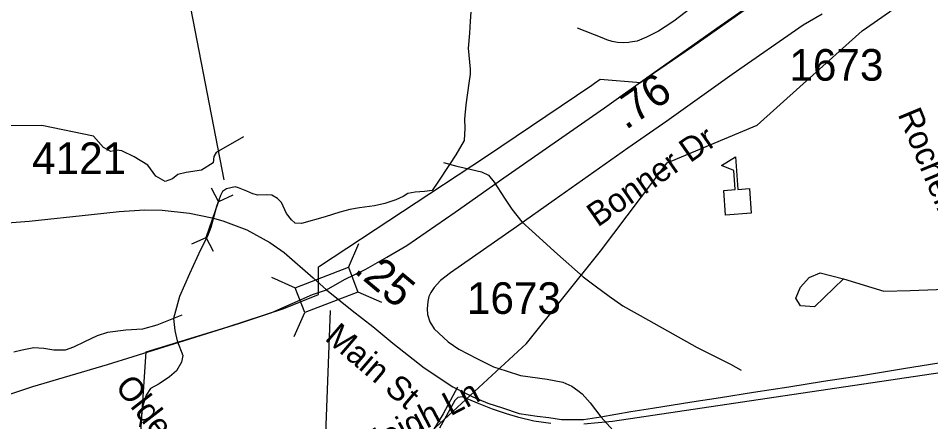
# Model space of a CAD drawing. Extents: x 1662474 to 1856135, y 779280 to 917889.
# Drawn here: x 1725036 to 1728645, y 818661 to 820256 of the extents above; entities that cross this region are included whole.
import ezdxf

# ---------------------------------------------------------------- set-up
doc = ezdxf.new("R2010")
doc.units = 0
for name, color, linetype in [('Exist Boundary Political City Limit New', 7, 'Continuous'), ('Exist Cultural Educational Facility High CELL', 7, 'Continuous'), ('Exist Hydrographic Creek Single Shore', 7, 'Continuous'), ('Exist Hydrographic Misc Water Feature', 7, 'Continuous'), ('Exist Railroad Mainline', 7, 'Continuous'), ('Exist Railroad Structure Bridge Number Label', 7, 'Continuous'), ('Exist Road Non-System Type 51', 7, 'Continuous'), ('Exist Road Non-System Type 51 Label', 7, 'Continuous'), ('Exist Road Secondary Mileage Hundredths English Label', 7, 'Continuous'), ('Exist Road Secondary Structure Culvert CELL', 7, 'Continuous'), ('Exist Road Secondary Structure Culvert Number Label', 7, 'Continuous'), ('Exist Road Secondary Structure RailRoad CELL', 7, 'Continuous'), ('Exist Road Secondary Type 51 Attributed', 7, 'Continuous'), ('Exist Road Secondary Type 51 Label', 7, 'Continuous'), ('Exist Road Secondary Type 51 Number Label', 7, 'Continuous'), ('Exist Utilities Electrical Transmission Line', 7, 'Continuous'), ('Map Preparation Boundary City Limit Buffer Line', 7, 'Continuous')]:
    doc.layers.add(name, color=color, linetype=linetype)

msp = doc.modelspace()

# ---------------------------------------------------------------- linework, layer by layer
at = {"layer": 'Exist Boundary Political City Limit New'}
for points in [[(1725521, 818621.9), (1725542, 818938.2), (1725684.2, 818981.4), (1725861.2, 819035.5), (1726086, 819108.9), (1726222.9, 819164.1), (1726223.8, 819273.9), (1726227.1, 819276), (1726883.2, 819708.8), (1727305, 819992.4), (1727314.8, 820000), (1727336.9, 820015.2), (1727496.4, 820002.2), (1727523.6, 820021.5), (1727698.1, 820142.2), (1728114.9, 820435.6)], [(1728753.6, 818865.6), (1727997.5, 818753.7), (1727386.4, 818662.2), (1727273.2, 818651.4)], [(1727141.9, 818654), (1727075.5, 818663), (1727015.8, 818677.4), (1726966.2, 818693), (1726911.8, 818711.2), (1726851.9, 818734.7), (1726793.4, 818759.4), (1726773.9, 818756.8), (1726767.4, 818750.2), (1726762.1, 818745), (1726702.4, 818635.8)]]:
    msp.add_lwpolyline(points, dxfattribs=at)
at = {"layer": 'Exist Cultural Educational Facility High CELL'}
msp.add_lwpolyline([(1727833, 819478.2), (1727825.9, 819575.8), (1727871.8, 819579.2), (1727866.3, 819654.1), (1727817.6, 819674.8), (1727872, 819708.1), (1727881.3, 819579.9), (1727927.3, 819583.2), (1727934.4, 819485.6)], close=True, dxfattribs=at)
at = {"layer": 'Exist Hydrographic Creek Single Shore'}
msp.add_lwpolyline([(1726826.2, 820280.7), (1726823.4, 820244.8), (1726820.2, 820197.2), (1726814.8, 820137.9), (1726823.6, 820054.7), (1726822.6, 820035.6), (1726817.4, 820000.1), (1726805.8, 819914), (1726800.8, 819857.3), (1726802.1, 819821.9), (1726799, 819772.8), (1726766.6, 819716.6), (1726741.8, 819678.3), (1726695.8, 819608.2), (1726673, 819576), (1726643, 819571.2), (1726606, 819568.4), (1726576.6, 819563.1), (1726558.5, 819551.3), (1726529.1, 819537.9), (1726486.1, 819523.8), (1726444.6, 819515.1), (1726385.6, 819506.9), (1726347.2, 819500.4), (1726308.1, 819489.9), (1726249.6, 819471), (1726155.6, 819445), (1726130.5, 819446.8), (1726116.5, 819458.9), (1726096.9, 819484.9), (1726076.6, 819527.4), (1726061.1, 819543.9), (1726039.1, 819556.8), (1726016.2, 819558.4), (1725982.8, 819556.8), (1725963.2, 819562.6), (1725939.6, 819572.3), (1725906.9, 819585.4), (1725893.2, 819590.1), (1725859.6, 819582), (1725843.4, 819571.2), (1725836, 819556), (1725828.9, 819536.6), (1725819.8, 819511.9), (1725797.1, 819429.5), (1725784.5, 819394.4), (1725756.1, 819340.6), (1725712.9, 819245.6), (1725673.8, 819156.8), (1725650.1, 819068.9), (1725655.6, 819021.6), (1725664.9, 818981.5), (1725686.6, 818922.7), (1725681.1, 818896.4), (1725661.8, 818862.3), (1725633.6, 818838.7), (1725592.9, 818811.7), (1725558.8, 818792.5), (1725542.2, 818766), (1725528.6, 818724.3), (1725515.5, 818641.1)], dxfattribs=at)
at = {"layer": 'Exist Hydrographic Misc Water Feature'}
for points in [[(1725926.6, 819787.1), (1725819, 819725), (1725809.9, 819709.9), (1725806.9, 819684.1), (1725759.9, 819655.4), (1725699.3, 819646.3), (1725666.8, 819638.7), (1725645.6, 819622), (1725616.8, 819611.4), (1725580.5, 819632.6), (1725548.6, 819675), (1725494.1, 819708.4), (1725446, 819732.6), (1725426.2, 819734.6), (1725402.1, 819729.6), (1725373.3, 819744.7), (1725333.9, 819790.2), (1725129.3, 819832.6), (1724852.4, 819830.5), (1724463.4, 820133.8), (1724422.4, 820144.5)], [(1726718.2, 819686), (1726770, 819671.5), (1726828.1, 819659), (1726867.9, 819648.5), (1726895.7, 819636.3), (1726917.5, 819608.1), (1726959.1, 819545.7), (1726988.4, 819501.4), (1727028, 819451), (1727067.8, 819414.6), (1727168.9, 819323.6), (1727270.2, 819234.7), (1727317.7, 819198.2), (1727373.3, 819157.7), (1727427, 819119.2), (1727528.5, 819062.2), (1727721.5, 818954.3), (1727852.9, 818889), (1727894.8, 818864.6)], [(1725683, 819082.8), (1725583.8, 819042.6), (1725527.6, 819027.1), (1725461.6, 819023.7), (1725389.4, 819014.4), (1725347.4, 819000.8), (1725297.2, 818977.3), (1725254.9, 818955.7), (1725220.7, 818944), (1725176.8, 818944.4), (1725136.8, 818950.8), (1725096.8, 818953.2), (1725050.7, 818943.6), (1725018.7, 818935.9)]]:
    msp.add_lwpolyline(points, dxfattribs=at)
at = {"layer": 'Exist Railroad Mainline'}
msp.add_lwpolyline([(1724843.4, 818717.3), (1725093.7, 818800.1), (1725388.2, 818887), (1725693.2, 818982), (1725911.7, 819051), (1726038.6, 819093.7), (1726200.2, 819163.9), (1726255, 819182.3), (1726326.3, 819223.2), (1726410.2, 819263.9), (1726493.2, 819311.9), (1726572.8, 819358.1), (1726764.2, 819490), (1726956.5, 819625.1), (1727353.9, 819902.1), (1727542.4, 820036.3), (1727798.6, 820217), (1727929.1, 820308.6)], dxfattribs=at)
at = {"layer": 'Exist Railroad Structure Bridge Number Label'}
msp.add_line((1726269.1, 819100.6), (1726182.8, 816731.3), dxfattribs=at)
at = {"layer": 'Exist Road Non-System Type 51'}
for points in [[(1727732.9, 820322.4), (1727696.1, 820296.4), (1727629.2, 820245.2), (1727594.5, 820222.1), (1727568, 820205.6), (1727536.9, 820189.1), (1727520.6, 820181.7), (1727484, 820165.8), (1727456, 820161.5), (1727450.4, 820160.8), (1727428.2, 820159.4), (1727406.1, 820160.8), (1727384.4, 820164.8), (1727363.1, 820171.4), (1727354.9, 820174.7), (1727344.9, 820179.1), (1727247.9, 820217.7)], [(1728299.4, 819226.4), (1728185, 819115.9), (1728129.6, 819120.1), (1728111, 819149.2), (1728129.6, 819193), (1728164, 819231.6), (1728206.8, 819250.2), (1728299.4, 819226.4)], [(1728299.4, 819226.4), (1728459.8, 819177.2), (1728562.9, 819180.7), (1728947.4, 819194.1)], [(1726772.9, 818797.8), (1726716.2, 818692.5), (1726630.4, 818551.4), (1726617.4, 818532.7), (1726608.1, 818522.7), (1726584.5, 818498), (1726546.1, 818470.2), (1726503.6, 818448.7), (1726458.8, 818434.8), (1726325.1, 818401.4), (1726185.6, 818376), (1726092.6, 818349.2), (1726047, 818331.4), (1725959.9, 818288.1), (1725873.2, 818232.9), (1725833.1, 818199.6)]]:
    msp.add_lwpolyline(points, dxfattribs=at)
at = {"layer": 'Exist Road Secondary Structure Culvert CELL'}
for p, q in [((1725799.1, 819586.2), (1725828, 819530.8)), ((1725884.9, 819556.6), (1725828, 819530.8)), ((1725779.5, 819390.1), (1725828, 819530.8)), ((1725722.7, 819364.3), (1725779.5, 819390.1)), ((1725808.4, 819334.8), (1725779.5, 819390.1))]:
    msp.add_line(p, q, dxfattribs=at)
at = {"layer": 'Exist Road Secondary Structure Culvert Number Label'}
msp.add_line((1725850.4, 819618.1), (1725348.7, 822208.2), dxfattribs=at)
at = {"layer": 'Exist Road Secondary Structure RailRoad CELL'}
for p, q in [((1726341.5, 819271.4), (1726383.4, 819365.4)), ((1726037, 819232.9), (1726131, 819191.1)), ((1726378.4, 819175.4), (1726472.4, 819133.5)), ((1726126.9, 818998.8), (1726168.7, 819092.8))]:
    msp.add_line(p, q, dxfattribs=at)
msp.add_lwpolyline([(1726131, 819191.1), (1726341.4, 819271.9), (1726379.1, 819173.6), (1726168.7, 819092.8)], close=True, dxfattribs=at)
at = {"layer": 'Exist Road Secondary Type 51 Attributed'}
for points in [[(1728215.5, 820271.8), (1728139.6, 820228.5), (1727858.9, 820034.1), (1727600.6, 819848.9), (1727446.9, 819742.5), (1727155.2, 819537.2), (1727005.9, 819432.2), (1726875.6, 819340.9), (1726745.5, 819250.3), (1726705.4, 819219), (1726680.3, 819192.4), (1726667.4, 819171.9), (1726660.2, 819156.1), (1726655.9, 819136.2), (1726653.2, 819107.9), (1726655, 819085.3), (1726663.7, 819056.4), (1726680.9, 819028), (1726735.5, 818977.1), (1726778.8, 818947.6), (1726849.3, 818911.6), (1726915.8, 818878.6), (1726966.1, 818862.2), (1727022, 818844.7), (1727127.4, 818829.7), (1727189, 818818.3), (1727225, 818801.4), (1727249.2, 818784.7), (1727266.2, 818771.5), (1727297.5, 818736.4), (1727340.2, 818680.6)], [(1723366.7, 818973), (1723410.9, 819020), (1723447, 819050.1), (1723470.4, 819062.4), (1723551.3, 819091), (1723686.3, 819136.1), (1723807.5, 819169.3), (1723871.1, 819185.2), (1723893.1, 819190.7), (1724026.2, 819224), (1724156.9, 819264.4), (1724318.5, 819319), (1724451.6, 819359.4), (1724630.7, 819400.8), (1724727.4, 819418.4), (1724817.7, 819427.9), (1724941.1, 819443.1), (1725078.6, 819453.7), (1725325.9, 819480.4), (1725435, 819491.9), (1725535.4, 819499.3), (1725604.4, 819497.5), (1725713.3, 819485.8), (1725802.6, 819466.9)], [(1725802.6, 819466.9), (1725845.2, 819456), (1725939.5, 819419.4), (1726031.2, 819370.1), (1726088.1, 819329.9), (1726201.8, 819230.3), (1726255, 819182.3), (1726356.2, 819100.8), (1726438.3, 819037.6), (1726516.9, 818971.8), (1726641.8, 818874.1), (1726754, 818798.9), (1726833.4, 818760), (1726892.7, 818734.9), (1726950.8, 818715.6), (1727017.5, 818693.7), (1727088.5, 818683.1), (1727134.4, 818677.6), (1727184, 818669.5), (1727222.6, 818670.3), (1727270.9, 818669.8), (1727340.2, 818680.6)], [(1727340.2, 818680.6), (1727458.5, 818701.1), (1727543.9, 818715.1), (1727699.3, 818740), (1727813.2, 818757.2), (1727943.8, 818778), (1728084, 818799), (1728220.5, 818822.1), (1728370.4, 818844.2), (1728544.4, 818872.6), (1728735.4, 818903.6)], [(1727467.6, 818529.2), (1727435.9, 818574.4), (1727340.2, 818680.6)]]:
    msp.add_lwpolyline(points, dxfattribs=at)
at = {"layer": 'Exist Utilities Electrical Transmission Line'}
msp.add_lwpolyline([(1723666.2, 815783.8), (1724225, 816289.8), (1724598.3, 816650.1), (1725333.8, 817353.7), (1726207.1, 818174.9), (1726600.6, 818559.1), (1727046.2, 818970.5), (1727339.2, 819336.1), (1727602, 819684.3), (1727958.2, 819833.3), (1728373.4, 820206.4), (1728482, 820282), (1728773.5, 820525.9), (1729250, 820911.2), (1729725.3, 821278.5)], dxfattribs=at)
at = {"layer": 'Map Preparation Boundary City Limit Buffer Line'}
for points in [[(1725521, 818621.9), (1725542, 818938.2), (1725684.2, 818981.4), (1725861.2, 819035.5), (1726086, 819108.9), (1726222.9, 819164.1), (1726223.8, 819273.9), (1726227.1, 819276), (1726883.2, 819708.8), (1727305, 819992.4), (1727314.8, 820000), (1727336.9, 820015.2), (1727496.4, 820002.2), (1727523.6, 820021.5), (1727698.1, 820142.2), (1728114.9, 820435.6)], [(1728753.6, 818865.6), (1727997.5, 818753.7), (1727386.4, 818662.2), (1727273.2, 818651.4)], [(1727141.9, 818654), (1727075.5, 818663), (1727015.8, 818677.4), (1726966.2, 818693), (1726911.8, 818711.2), (1726851.9, 818734.7), (1726793.4, 818759.4), (1726773.9, 818756.8), (1726767.4, 818750.2), (1726762.1, 818745), (1726702.4, 818635.8)]]:
    msp.add_lwpolyline(points, dxfattribs=at)

# ---------------------------------------------------------------- texts
at = {"layer": 'Exist Road Non-System Type 51 Label'}
for s, rotation, p in [('Rochelle Rd', 292.5556, (1728513.1, 819877.4)), ('Olde England Ct', 307.8593, (1725415.6, 818799.6)), ('Yorkleigh Ln', 27.5372, (1726244.2, 818420.9))]:
    msp.add_text(s, height=95, rotation=rotation, dxfattribs=at).set_placement(p)
at = {"layer": 'Exist Road Secondary Mileage Hundredths English Label'}
for s, rotation, p in [('.76', 34.7093, (1727438.7, 819812.8)), ('.25', 320.0898, (1726358.6, 819254.5))]:
    msp.add_text(s, height=125, rotation=rotation, dxfattribs=at).set_placement(p)
at = {"layer": 'Exist Road Secondary Type 51 Label'}
for s, rotation, p in [('Bonner Dr', 34.8335, (1727327.5, 819428.3)), ('Main St', 319.443, (1726244.1, 818986.9))]:
    msp.add_text(s, height=95, rotation=rotation, dxfattribs=at).set_placement(p)
at = {"layer": 'Exist Road Secondary Type 51 Number Label'}
for s, p in [('1673', (1728085.8, 820009.5)), ('4121', (1725090.6, 819640.4)), ('1673', (1726810.4, 819087.5))]:
    msp.add_text(s, height=125, dxfattribs=at).set_placement(p)

doc.saveas('drawing.dxf')
